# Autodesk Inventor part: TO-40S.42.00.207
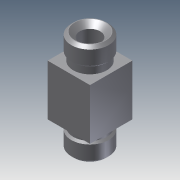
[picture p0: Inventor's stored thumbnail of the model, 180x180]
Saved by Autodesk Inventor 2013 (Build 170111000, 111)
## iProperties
Shininess: 64.0
Angle Display Precision: 2
Document Length Units: 11269
Document Angle Units: 11279
Document Time Units: 11290
Document Mass Units: 11283
Document Length Units Precision: 3
Document Angle Units Precision: 2
Created: 2002-02
Part Number: TO-40S.42.00.207
Document SubType Name: Modeling
Designer: TEvgeniy
Density: 1 g/cm^3
Material: Generic
Mass: 20.5519 g
Surface Area: 84.0708 cm^2
Volume: 20.5519 cm^3
Density: 0.0
Volumn: 0.0
Area: 0.0
PropertySet Name: Model Information
Control State: 0
Master: False
Checked Out: False
Checked Out Date: 2008-10-15
Last Check In Date: 2008-10-15
Author: TEvgeniy
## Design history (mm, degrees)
node "WorkPlane1"
sketch "Sketch1"
  geometry: L1 (182.778, 133.836)-(157.778, 133.836); L2 (182.778, 108.836)-(182.778, 133.836); L3 (157.778, 108.836)-(182.778, 108.836); L4 (157.778, 133.836)-(157.778, 108.836)
  constraints: 8 end point, 2 horizontal, 2 vertical, 1 other
  dimensions: "d1" = 25 distance of L1.start L1.end; "d3" = 25 distance of L2.start L1.start
extrude "ExtrusionBlind1" new body sketch "Sketch1" distance "d4" = 60; taper "d5" = 0 deg
node "WorkAxis1"
node "WorkPlane2"
revolve "RevolutionAngle1" stored, may be unused: angle "d27" = 360 deg
revolve "RevolutionAngle2" stored, may be unused: angle "d37" = 360 deg
revolve "RevolutionAngle3" stored, may be unused: angle "d47" = 360 deg
revolve "RevolutionAngle4" stored, may be unused: angle "d52" = 360 deg
revolve "RevolutionAngle5" stored, may be unused: angle "d62" = 360 deg
body "Solid1"
sketch "Sketch2"
  geometry: L1 (182.778, 133.836)-(182.778, 108.836) reference; L2 (182.778, 108.836)-(157.778, 108.836) reference; 1 further point
  dimensions: "d8" = 12.5 distance from line of L1 point (170.278, 121.336); "d10" = 12.5 distance from line of L2 point (170.278, 121.336)
hole "Hole1" sketch "Sketch2" diameter "d11" = 12; stored, may be unused: countersink angle "d15" = 82 deg, drill point angle "d17" = 118 deg; dims "d12" = 6, "d13" = 4, "d14" = 2, "d16" = 8
chamfer "Chamfer1" distance "d38" = 1.6; stored, may be unused: angle "d39" = 45 deg, second distance "d63" = 1.6
chamfer "Chamfer2" distance "d40" = 1.6; stored, may be unused: angle "d41" = 45 deg, second distance "d64" = 1.6
workplane "Work Plane3"
sketch "Sketch3"
  geometry: L1 (19.9, 9.642)-(19.9, 24.642); L2 (11, 9.642)-(19.9, 9.642); L3 (11, 19.542)-(11, 9.642); L4 (9.9, 20.642)-(11, 19.542); L5 (9.9, 24.642)-(9.9, 20.642); L6 (19.9, 24.642)-(9.9, 24.642); L7 (6, 9.642)-(-6, 9.642) reference; L8 (0, 4.821)-(0, 74.463)
  constraints: 14 end point, 3 vertical, 2 horizontal
  dimensions: "d20" = 15 distance of L1.start L1.end; "d22" = 4 distance of L5.start L4.start; "d24" = 45 deg angle of L4 L3; "d26" = 10 distance of L1.end L5.start
sketch "Sketch4"
  geometry: L1 (19.9, 69.642)-(19.9, 54.642); L2 (11, 69.642)-(19.9, 69.642); L3 (11, 59.742)-(11, 69.642); L4 (9.9, 58.642)-(11, 59.742); L5 (9.9, 54.642)-(9.9, 58.642); L6 (19.9, 54.642)-(9.9, 54.642); L7 (0, 4.821)-(0, 74.463); 1 further point
  constraints: 14 end point, 3 vertical, 2 horizontal
  dimensions: "d29" = 15 distance of L1.start L1.end; "d31" = 10 distance of L1.end L5.start; "d33" = 4 distance of L5.start L4.start; "d35" = 45 deg angle of L3 L4
sketch "Sketch5"
  geometry: L1 (0, 60.642)-(9, 69.642); L2 (0, 69.642)-(0, 60.642); L3 (9, 69.642)-(0, 69.642); L4 (-9.4, 69.642)-(9.4, 69.642) reference; L5 (0, 4.821)-(0, 74.463)
  constraints: 8 end point, 1 horizontal, 1 vertical
  dimensions: "d43" = 9 distance of L1.end L2.start; "d45" = 45 deg angle of L3 L1
sketch "Sketch6"
  geometry: L1 (0, 18.642)-(9, 9.642); L2 (0, 9.642)-(0, 18.642); L3 (9, 9.642)-(0, 9.642); L4 (9.4, 9.642)-(-9.4, 9.642) reference; L5 (0, 4.821)-(0, 74.463)
  constraints: 8 end point, 1 horizontal, 1 vertical
  dimensions: "d49" = 9 distance of L1.end L2.start; "d51" = 9 distance of L2.start L1.start
sketch "Sketch7"
  geometry: L1 (0, 39.642)-(12.5, 39.642); L2 (0, 33.642)-(0, 39.642); L3 (10.5, 33.642)-(0, 33.642); L4 (10.5, 27.142)-(10.5, 33.642); L5 (12.5, 27.142)-(10.5, 27.142); L6 (12.5, 39.642)-(12.5, 27.142); L7 (-9, 69.642)-(9, 69.642) reference; L8 (0, 39.642)-(12.5, 39.642); 1 further point
  constraints: 14 end point, 3 horizontal, 3 vertical
  dimensions: "d54" = 12.5 distance of L1.end L5.start; "d56" = 6 distance of L2.start L1.start; "d59" = 2 distance of L5.start L4.start; "d61" = 12.5 distance of L1.start L1.end
other parameters: "d0" = 25 (derived), "d2" = 25 (derived), "d6" = 0, "d7" = 12.5 (derived), "d9" = 12.5 (derived), "d18" = 0, "d19" = 15 (derived), "d21" = 4 (derived), "d23" = 45 deg (derived), "d28" = 15 (derived), "d32" = 4 (derived), "d34" = 45 deg (derived), "d36" = 0 (derived), "d42" = 9 (derived), "d44" = 45 deg (derived), "d46" = 0 (derived), "d48" = 9 (derived), "d50" = 9 (derived), "d53" = 12.5 (derived), "d55" = 6 (derived), "d57" = 0 (derived), "d58" = 2 (derived), "d60" = 12.5 (derived)
